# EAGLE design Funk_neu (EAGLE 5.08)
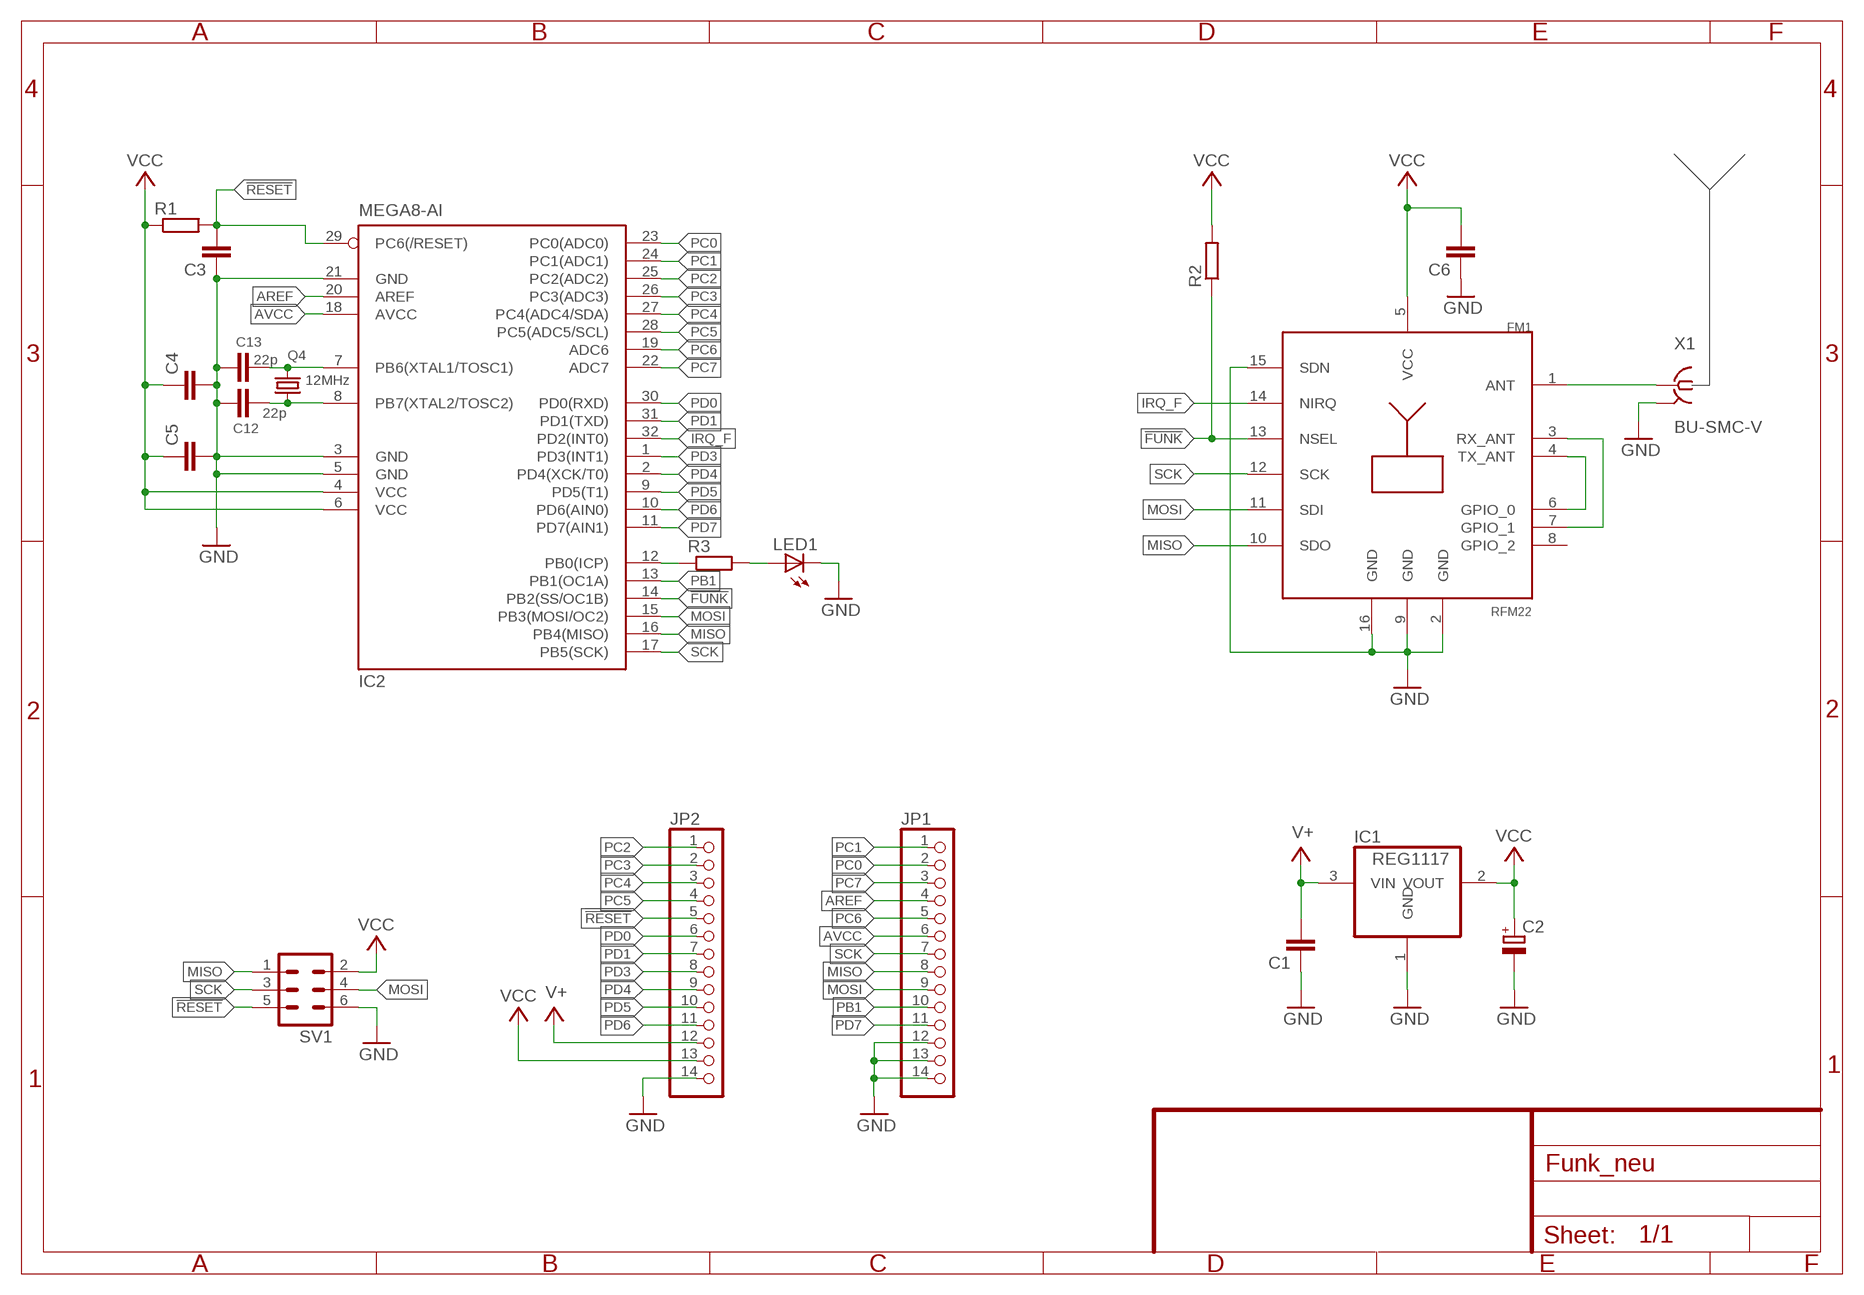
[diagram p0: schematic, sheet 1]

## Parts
C1  C-EUC0805  [C0805]
C2  CPOL-EUSMCB  [SMC_B]
C3  C-EUC0805  [C0805]
C4  C-EUC0805  [C0805]
C5  C-EUC0805  [C0805]
C6  C-EUC0805  [C0805]
C12  22p  C-EUC0805  [C0805]
C13  22p  C-EUC0805  [C0805]
FM1  RFM22  [RFM22]
IC1  REG1117  [SOT223]
IC2  MEGA8-AI  [TQFP32-08]
JP1  PINHD-1X14  [1X14]
JP2  PINHD-1X14  [1X14]
LED1  LEDSMT1206  [1206]
Q4  12MHz  CRYSTALCTS406  [CTS406]
R1  R-EU_R0805  [R0805]
R2  R-EU_R0805  [R0805]
R3  R-EU_R0805  [R0805]
SV1  ML6  [ML6]
X1  BU-SMC-V  [BU-SMC-V]

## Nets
!FUNK: FM1.13(NSEL) IC2.14(PB2(SS/OC1B)) R2.1
!RESET: C3.2 IC2.29(PC6(/RESET)) JP2.5 R1.2 SV1.5
AREF: IC2.20(AREF) JP1.4
AVCC: IC2.18(AVCC) JP1.6
GND: C1.1 C2.- C3.1 C4.2 C5.2 C6.1 C12.1 C13.1 FM1.2(GND) FM1.9(GND) FM1.15(SDN) FM1.16(GND) IC1.1(GND) IC2.3(GND) IC2.5(GND) IC2.21(GND) JP1.12 JP1.13 JP1.14 JP2.14 LED1.C SV1.6 X1.2(GND)
IRQ_F: FM1.14(NIRQ) IC2.32(PD2(INT0))
MISO: FM1.10(SDO) IC2.16(PB4(MISO)) JP1.8 SV1.1
MOSI: FM1.11(SDI) IC2.15(PB3(MOSI/OC2)) JP1.9 SV1.4
N$1: FM1.4(TX_ANT) FM1.6(GPIO_0)
N$3: FM1.3(RX_ANT) FM1.7(GPIO_1)
N$4: FM1.1(ANT) X1.1
N$18: IC2.12(PB0(ICP)) R3.1
N$19: LED1.A R3.2
N$26: C13.2 IC2.7(PB6(XTAL1/TOSC1)) Q4.3
N$27: C12.2 IC2.8(PB7(XTAL2/TOSC2)) Q4.1
PB1: IC2.13(PB1(OC1A)) JP1.10
PC0: IC2.23(PC0(ADC0)) JP1.2
PC1: IC2.24(PC1(ADC1)) JP1.1
PC2: IC2.25(PC2(ADC2)) JP2.1
PC3: IC2.26(PC3(ADC3)) JP2.2
PC4: IC2.27(PC4(ADC4/SDA)) JP2.3
PC5: IC2.28(PC5(ADC5/SCL)) JP2.4
PC6: IC2.19(ADC6) JP1.5
PC7: IC2.22(ADC7) JP1.3
PD0: IC2.30(PD0(RXD)) JP2.6
PD1: IC2.31(PD1(TXD)) JP2.7
PD3: IC2.1(PD3(INT1)) JP2.8
PD4: IC2.2(PD4(XCK/T0)) JP2.9
PD5: IC2.9(PD5(T1)) JP2.10
PD6: IC2.10(PD6(AIN0)) JP2.11
PD7: IC2.11(PD7(AIN1)) JP1.11
SCK: FM1.12(SCK) IC2.17(PB5(SCK)) JP1.7 SV1.3
V+: C1.2 IC1.3(VIN) JP2.12
VCC: C2.+ C4.1 C5.1 C6.2 FM1.5(VCC) IC1.2(VOUT) IC2.4(VCC) IC2.6(VCC) JP2.13 R1.1 R2.2 SV1.2
Unconnected: FM1.8(GPIO_2)

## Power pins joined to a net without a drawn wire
GND: X1.3(GND) X1.4(GND) X1.5(GND)

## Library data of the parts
C1 C3-C6 C12 C13 = rcl:C-EU: CAPACITOR, European symbol
C2 = rcl:CPOL-EU: POLARIZED CAPACITOR, European symbol
FM1 = RFMxx:RFM22
IC1 = burr-brown:REG1117: 800mA and 1A Low Dropout (LDO) Positive Regulator 1.8V, 2.5V, 2.85V, 3.3V, 5V, and Adj
IC2 = atmel:MEGA8: MICROCONTROLLER 8 Kbytes FLASH, 1 kbytes SRAM, 512 bytes EEPROM, USART, 6-channel 10 bit ADC, 2-channel 8 bit ADC Pin compatible with Atmega48, ATMega88, ATMega168 Source: avr.lbr
JP1 JP2 = pinhead:PINHD-1X14: PIN HEADER
LED1 = led:LED: LED
Q4 = crystal:CRYSTAL: CRYSTAL
R1-R3 = rcl:R-EU_: RESISTOR, European symbol
SV1 = con-harting-ml:ML6: HARTING
X1 = con-coax:BU-SMC-V: FEMALE SMC CONNECTOR Radiall R112 426 distributor RS 295-5429

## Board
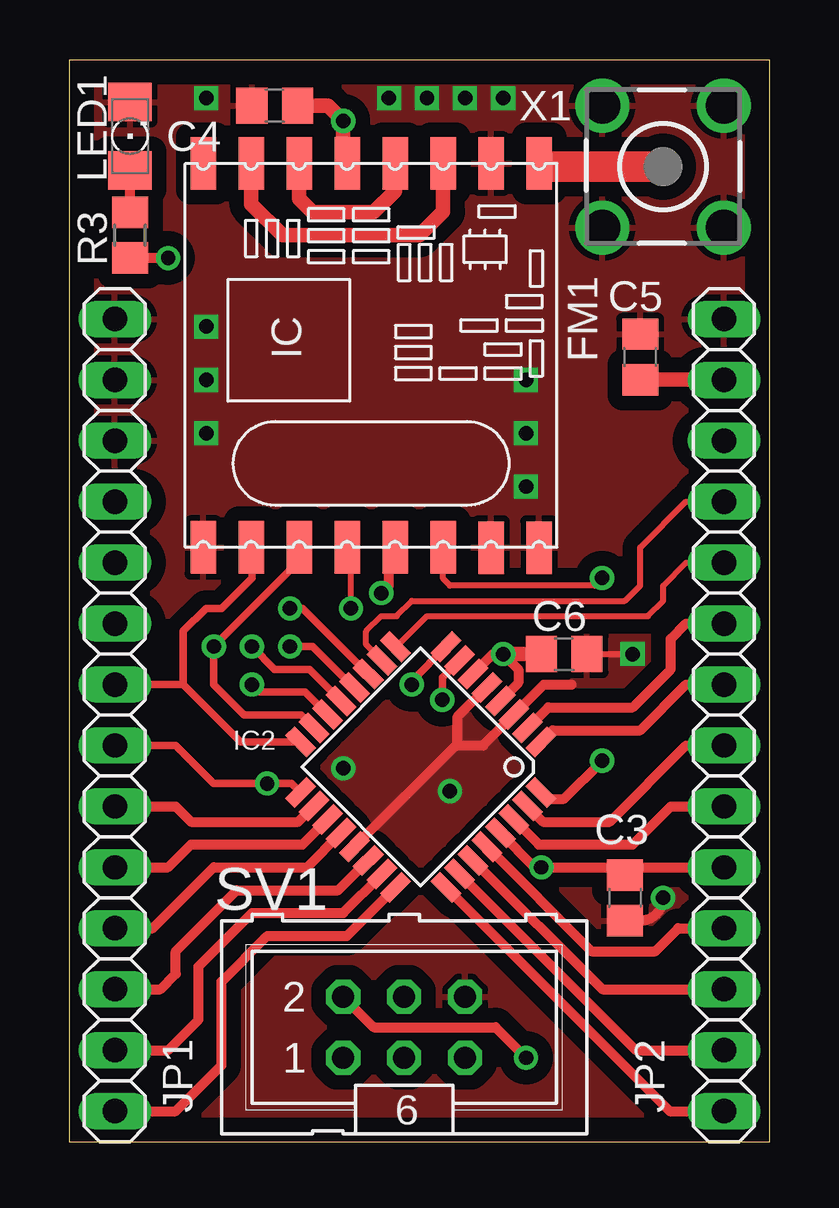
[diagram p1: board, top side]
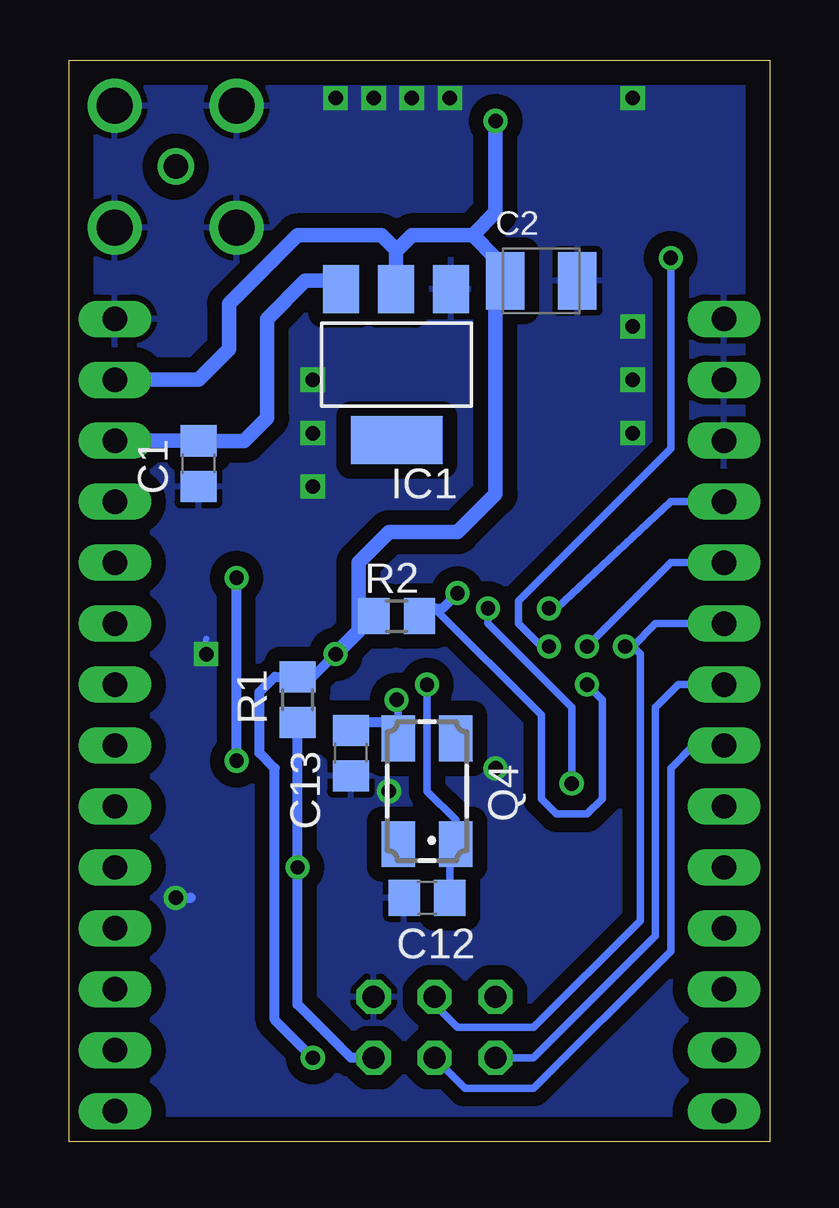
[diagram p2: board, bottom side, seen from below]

Size 29.21 x 45.09 mm. Coordinates in mm from the lower left corner, seen from the top.
Outline: 0,0 29.21,0 29.21,45.09 0,45.09 0,0
Copper layers (1*16): Top 0.035mm / dielectric 1.5mm / Bottom 0.035mm
Design rules "default": minimum track width 10mil, minimum drill 24mil, track to track 8mil, track to pad 8mil, pad to pad 8mil, via to via 8mil, smd to smd 8mil, copper to edge 40mil, drill to drill 8mil, minimum pad ring 10mil, minimum via ring 8mil, stop-mask expansion 4mil, vias tented up to drill 0mil, thermal gap 10mil

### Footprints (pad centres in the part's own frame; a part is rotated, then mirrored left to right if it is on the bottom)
C0805 = smd 1.3 x 1.5: 1 -0.95,0; 2 0.95,0
SMC_B = smd 1.6 x 2.4: + -1.5,0; - 1.5,0
RFM22 = smd 2.184 x 1.067: 1 -8.38,5.62; 2 -8.38,3.62; 3 -8.38,1.62; 4 -8.38,-0.38; 5 -8.38,-2.38; 6 -8.38,-4.38; 7 -8.38,-6.38; 8 -8.38,-8.38; 9 7.62,-8.38; 10 7.62,-6.38; 11 7.62,-4.38; 12 7.62,-2.38; 13 7.62,-0.38; 14 7.62,1.62; 15 7.625,3.625; 16 7.625,5.625
SOT223 = smd 1.499 x 2.007: 1 -2.261,-3.15; 2 0.025,-3.15; 3 2.311,-3.15 | smd 3.81 x 2.007: 4 0,3.15
TQFP32-08 = smd 1.27 x 0.559: 1 -4.293,2.8; 2 -4.293,2; 3 -4.293,1.2; 4 -4.293,0.4; 5 -4.293,-0.4; 6 -4.293,-1.2; 7 -4.293,-2; 8 -4.293,-2.8; 17 4.293,-2.8; 18 4.293,-2; 19 4.293,-1.2; 20 4.293,-0.4; 21 4.293,0.4; 22 4.293,1.2; 23 4.293,2; 24 4.293,2.8 | smd 0.559 x 1.27: 9 -2.8,-4.293; 10 -2,-4.293; 11 -1.2,-4.293; 12 -0.4,-4.293; 13 0.4,-4.293; 14 1.2,-4.293; 15 2,-4.293; 16 2.8,-4.293; 25 2.8,4.293; 26 2,4.293; 27 1.2,4.293; 28 0.4,4.293; 29 -0.4,4.293; 30 -1.2,4.293; 31 -2,4.293; 32 -2.8,4.293
1X14 = drill 1.016 long: 1 -16.51,0; 2 -13.97,0; 3 -11.43,0; 4 -8.89,0; 5 -6.35,0; 6 -3.81,0; 7 -1.27,0; 8 1.27,0; 9 3.81,0; 10 6.35,0; 11 8.89,0; 12 11.43,0; 13 13.97,0; 14 16.51,0
1206 = smd 1.6 x 1.803: A -1.422,0; C 1.422,0
CTS406 = smd 1.9 x 1.4: 1 -2.2,-1.2; 2 2.2,-1.2; 3 2.2,1.2; 4 -2.2,1.2
R0805 = smd 1.3 x 1.5: 1 -0.95,0; 2 0.95,0
ML6 = drill 0.914 octagon: 1 -2.54,-1.27; 2 -2.54,1.27; 3 0,-1.27; 4 0,1.27; 5 2.54,-1.27; 6 2.54,1.27
BU-SMC-V = drill 1.016 round: 1 0,0 | drill 1.5 round: 2 -2.54,2.54; 3 2.54,2.54; 4 2.54,-2.54; 5 -2.54,-2.54

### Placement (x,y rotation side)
C1  23.81,28.26 90 bottom
C2  9.53,35.88 0 bottom
C3  23.18,10.16 90 top
C4  8.57,43.18 180 top
C5  23.81,32.7 90 top
C6  20.64,20.32 180 top
C12  14.29,10.16 0 bottom
C13  17.46,16.19 90 bottom
FM1  13.97,32.38 270 top
IC1  15.56,32.38 180 bottom
IC2  14.66,15.61 225 top
JP1  1.91,17.78 90 top
JP2  27.3,17.78 90 top
LED1  2.54,41.91 90 top
Q4  14.29,14.61 90 bottom
R1  19.69,18.41 270 bottom
R2  15.56,21.91 180 bottom
R3  2.54,37.78 90 top
SV1  13.97,4.76 0 top
X1  24.77,40.64 90 top

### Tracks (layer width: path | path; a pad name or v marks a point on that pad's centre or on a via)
!FUNK  (via drill 0.6)
  Top 0.305: IC2.14 9.84,18.73 7.94,18.73 v7.62,19.05
  Top 0.406: v13.02,22.86 13.33,23.18 13.33,24.45 13.59,24.7 13.65,24.7 FM1.13
  Bottom 0.254: 14.6,21.59 14.6,22.22 R2.1
  Bottom 0.305: v7.62,19.05 6.99,18.41 6.99,14.29 7.62,13.65 8.89,13.65 9.53,14.29 9.53,17.78 13.97,22.22 14.6,22.22 14.6,21.59
  Bottom 0.406: R2.1 14.29,22.22 13.97,22.22 13.65,22.22 v13.02,22.86
!RESET  (via drill 0.6)
  Top 0.406: 22.86,11.43 JP2.5 | 22.86,11.43 v19.69,11.43 19.41,11.43 IC2.29 17.94,12.86 | 22.86,11.43 arc-90 C3.2
  Bottom 0.406: R1.2 v19.69,11.43 19.69,5.71 17.46,3.49 SV1.5
AREF
  Top 0.406: IC2.20 9.91,11.43 6.03,11.43 3.49,8.89 JP1.4
AVCC
  Top 0.406: IC2.18 9.55,13.33 5.08,13.33 4.45,13.97 JP1.6
GND  (via drill 0.6)
  Top 0.254: C6.1 v23.5,20.32
  Top 0.406: IC2.21 16.19,16.58 | 16.19,16.58 16.19,16.51 17.25,16.51 IC2.3 19.8,19.05 20.96,19.05 | IC2.5 16.19,17.71 16.19,16.58 | C3.1 23.82,9.21 arc90 v24.77,10.16
  Bottom 0.254: v23.5,20.32 23.5,20.95
  Bottom 0.406: v24.77,10.16 24.13,10.16
  other vias: 5.71,43.5 11.43,15.56 5.71,33.97 5.71,31.75 5.71,29.53 19.05,31.75 19.05,29.53 19.05,27.3 13.33,43.5 14.92,43.5 16.51,43.5 18.1,43.5 15.88,14.61
  pour Bottom (isolate 0.61): 0,45.09 29.21,45.09 29.21,0 0,0
  pour Top (isolate 0.61): 0,45.09 29.21,45.09 29.21,0 0,0
IRQ_F  (via drill 0.6)
  Top 0.254: FM1.14 15.59,23.46 15.88,23.18 21.91,23.18 v22.23,23.5
  Top 0.305: IC2.32 19.94,14.29
  Top 0.406: 19.94,14.29 20.64,14.29 v22.23,15.88
  Bottom 0.406: v22.23,15.88 v22.23,23.5
MISO
  Top 0.305: IC2.16 7.15,16.67 4.76,19.05 | JP1.8 4.76,19.05 | 4.76,19.05 4.76,21.27 5.71,22.22 6.35,22.22 7.62,23.5 7.62,24.73 FM1.10
  Bottom 0.305: SV1.1 9.84,3.49 4.76,8.57 4.76,18.1 3.81,19.05 JP1.8
MOSI  (via drill 0.6)
  Top 0.254: 9.27,23.88 9.59,23.88 FM1.11
  Top 0.305: IC2.15 9.66,17.78 7.3,17.78 6.03,19.05 v6.03,20.64 9.27,23.88
  Bottom 0.254: 5.71,20.64 v6.03,20.64
  Bottom 0.305: 5.71,20.64 4.76,21.59 JP1.9 | SV1.4 13.97,5.71 13.02,4.76 9.84,4.76 5.4,9.21 5.4,20.32 5.71,20.64 | 5.71,20.64 v6.03,20.64
N$1
  Top 0.61: FM1.6 9.59,39.3 10.16,38.74 12.7,38.74 13.59,39.62 FM1.4
N$3
  Top 0.61: FM1.7 7.59,39.08 8.89,37.78 14.6,37.78 15.59,38.77 FM1.3
N$4
  Top 0.406: FM1.1 19.69,39.91 19.69,40.64
  Top 1.27: 19.69,40.64 X1.1
N$18  (via drill 0.6)
  Top 0.305: 11.87,18.93 10.16,20.64 v9.21,20.64
  Top 0.406: R3.1 v4.13,36.83 | IC2.12 11.87,18.93
  Bottom 0.305: v9.21,20.64 9.53,20.64 10.48,21.59 10.48,22.54 4.13,28.89 v4.13,36.83
N$19
  Top 0.406: R3.2 LED1.A
N$26  (via drill 0.6)
  Top 0.305: IC2.7 15.56,19.34 v15.56,18.41
  Bottom 0.305: Q4.3 15.49,18.34 | 16.19,17.46 15.88,17.46 15.56,17.46
  Bottom 0.406: 15.49,18.34 v15.56,18.41 | Q4.3 15.56,17.19 15.56,17.46 | 15.88,17.46 17.14,17.46 C13.2
N$27  (via drill 0.6)
  Top 0.305: IC2.8 14.29,19.2 v14.29,19.05
  Bottom 0.305: v14.29,19.05 14.29,14.61 13.09,13.4 Q4.1 | C12.2 13.34,12.47
  Bottom 0.406: 13.34,12.47 Q4.1
PB1  (via drill 0.6)
  Top 0.305: IC2.13 10.02,19.68 8.57,19.68 v7.62,20.64
  Bottom 0.305: v7.62,20.64 4.13,24.13 JP1.10
PC0
  Top 0.406: IC2.23 13.04,11.13 11.43,9.53 7.62,9.53 5.4,7.3 5.4,5.08 4.13,3.81 JP1.2
PC1
  Top 0.406: IC2.24 11.58,8.57 8.25,8.57 6.35,6.67 6.35,3.17 4.45,1.27 JP1.1
PC2
  Top 0.406: IC2.25 25.04,1.27 JP2.1
PC3
  Top 0.406: IC2.26 23.63,3.81 JP2.2
PC4
  Top 0.406: IC2.27 22.22,6.35 JP2.3
PC5
  Top 0.406: IC2.28 21.77,7.94 24.45,7.94 25.4,8.89 JP2.4
PC6
  Top 0.406: IC2.19 9.73,12.38 5.08,12.38 4.13,11.43 JP1.5
PC7
  Top 0.406: IC2.22 11.22,10.48 6.99,10.48 4.45,7.94 4.45,6.98 3.81,6.35 JP1.3
PD0
  Top 0.406: IC2.30 19.59,12.38 23.5,12.38 25.08,13.97 JP2.6
PD1
  Top 0.406: IC2.31 19.77,13.33 22.54,13.33 25.72,16.51 JP2.7
PD3
  Top 0.406: IC2.1 20.15,17.14 23.81,17.14 25.72,19.05 JP2.8
PD4
  Top 0.406: IC2.2 19.97,18.1 23.5,18.1 25.08,19.68 25.08,20.95 25.72,21.59 JP2.9
PD5
  Top 0.254: IC2.9 13.64,20.63 14.92,21.91 23.5,21.91 24.13,21.91 24.77,22.54 24.77,23.18 25.72,24.13 JP2.10
PD6
  Top 0.254: IC2.10 12.38,20.72 12.38,21.27 13.02,21.91 13.65,21.91 14.29,22.54 23.18,22.54 23.81,23.18 23.81,24.77 25.72,26.67 JP2.11
PD7  (via drill 0.6)
  Top 0.305: IC2.11 9.74,22.22 v9.21,22.22
  Bottom 0.305: v9.21,22.22 8.89,22.22 4.13,26.67 JP1.11
SCK  (via drill 0.6)
  Top 0.254: FM1.12 11.75,24.92 v11.75,22.22
  Top 0.305: IC2.17 9.28,14.92 v8.25,14.92 6.03,14.92 4.45,16.51 JP1.7
  Bottom 0.305: v8.25,14.92 8.25,18.1 11.75,21.59 v11.75,22.22 | SV1.3 12.7,2.22 9.84,2.22 4.13,7.94 4.13,15.56 3.17,16.51 JP1.7
V+
  Bottom 0.406: C1.2 23.18,29.21 | 18.53,35.88 IC1.3
  Bottom 0.61: 23.18,29.21 JP2.12 | C1.2 21.91,29.21 20.96,30.16 20.96,34.29 19.37,35.88 18.53,35.88
VCC  (via drill 0.6)
  Top 0.406: IC2.4 18.73,19.12 18.73,19.68 v18.1,20.32 17.67,20.32 IC2.6 | SV1.2 12.7,4.76 17.78,4.76 v19.05,3.49
  Top 0.61: FM1.5 11.59,40.16 11.43,40.32 v11.43,42.55 10.79,43.18 C4.1 | v18.1,20.32 C6.2 | C5.1 JP2.13
  Bottom 0.305: R2.2 16.82,22.22 17.14,22.22
  Bottom 0.406: v18.1,20.32 19.05,19.37 R1.1 20.64,19.37 21.27,18.73 21.27,16.19 20.64,15.56 20.64,5.08 v19.05,3.49
  Bottom 0.61: v11.43,42.55 11.43,38.74 12.38,37.78 | v18.1,20.32 17.14,21.27 17.14,22.22 17.14,24.13 15.88,25.4 13.02,25.4 11.43,26.99 11.43,36.2 | 12.38,37.78 14.92,37.78 15.58,37.12 IC1.2 15.58,37.17 16.19,37.78 19.69,37.78 22.54,34.93 22.54,33.02 C5.1 JP2.13 | 12.38,37.78 11.43,36.83 11.43,36.2 | C2.+ 11.11,35.88 11.43,36.2

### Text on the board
tTest: GND | GND | GND | Vout (+3,3V) | GND | Vin | PD7(AIN1) | PD6(AIN0) | PB1(OC1A) | PD5(T1) | PB3(MOSI) | PD4(XCK/T0) | PB4(MISO) | PD3(INT1) | PB5(SCK) | PD1(TXD) | AVCC | PD0(RXD) | PC6(ADC6) | !RESET | AREF | PC5(ADC5/SCL) | PC7(ADC7) | PC4(ADC4/SDA) | PC0(ADC0) | PC3(ADC3) | PC1(ADC1) | PC2(ADC2)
